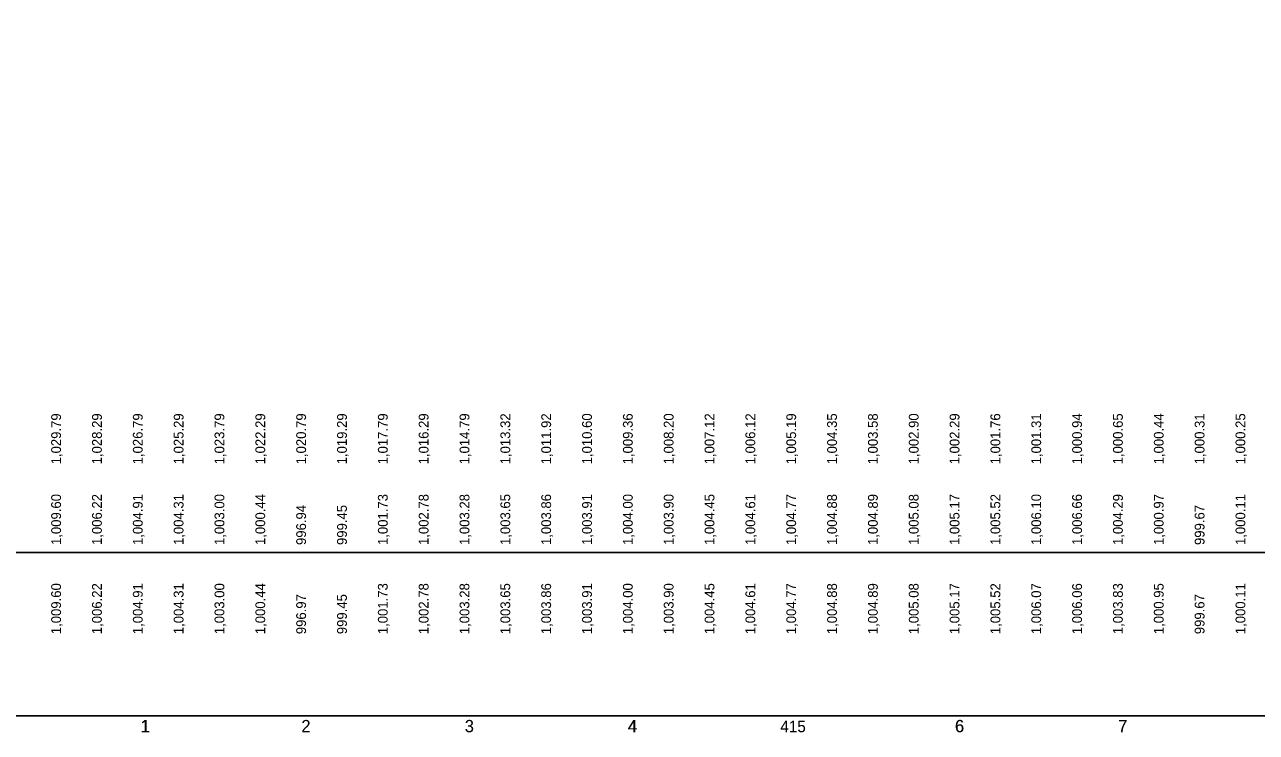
# Model space of a CAD drawing. Extents: x 150 to 16976893, y 3102 to 12559827.
# Drawn here: x 16975421 to 16976175, y 12558429 to 12558863 of the extents above; entities that cross this region are included whole.
import ezdxf

# ---------------------------------------------------------------- set-up
doc = ezdxf.new("R2010")
doc.units = 0
for name, color, linetype in [('Default', 7, 'Continuous'), ('Level 56', 7, 'Continuous'), ('RD_DDB_StaTX', 7, 'Continuous'), ('RD_DDB_StripGrade_EX', 7, 'Continuous'), ('RD_GPK_Profile_Cell', 7, 'Continuous')]:
    doc.layers.add(name, color=color, linetype=linetype)

msp = doc.modelspace()

# ---------------------------------------------------------------- linework, layer by layer
at = {"layer": 'Default'}
msp.add_lwpolyline([(16975392.9, 12558539.31), (16976892.9, 12558539.31), (16976892.9, 12559537.53), (16975392.9, 12559537.53)], close=True, dxfattribs=at)
at = {"layer": 'RD_GPK_Profile_Cell'}
msp.add_line((16972208.1, 12558439.31), (16976677.07, 12558439.31), dxfattribs=at)

# ---------------------------------------------------------------- texts
at = {"layer": 'Level 56'}
for s, p in [('1,029.79', (16975442.9, 12558593.29)), ('1,028.29', (16975467.9, 12558593.29)), ('1,026.79', (16975492.9, 12558593.29)), ('1,025.29', (16975517.9, 12558593.29)), ('1,023.79', (16975542.9, 12558593.29)), ('1,022.29', (16975567.9, 12558593.29)), ('1,020.79', (16975592.9, 12558593.29)), ('1,019.29', (16975617.9, 12558593.29)), ('1,017.79', (16975642.9, 12558593.29)), ('1,016.29', (16975667.9, 12558593.29)), ('1,014.79', (16975692.9, 12558593.29)), ('1,013.32', (16975717.9, 12558593.29)), ('1,011.92', (16975742.9, 12558593.29)), ('1,010.60', (16975767.9, 12558593.29)), ('1,009.36', (16975792.9, 12558593.29)), ('1,008.20', (16975817.9, 12558593.29)), ('1,007.12', (16975842.9, 12558593.29)), ('1,006.12', (16975867.9, 12558593.29)), ('1,005.19', (16975892.9, 12558593.29)), ('1,004.35', (16975917.9, 12558593.29)), ('1,003.58', (16975942.9, 12558593.29)), ('1,002.90', (16975967.9, 12558593.29)), ('1,002.29', (16975992.9, 12558593.29)), ('1,001.76', (16976017.9, 12558593.29)), ('1,001.31', (16976042.9, 12558593.29)), ('1,000.94', (16976067.9, 12558593.29)), ('1,000.65', (16976092.9, 12558593.29)), ('1,000.44', (16976117.9, 12558593.29)), ('1,000.31', (16976142.9, 12558593.29)), ('1,000.25', (16976167.9, 12558593.29)), ('1,009.60', (16975442.9, 12558489.31)), ('1,006.22', (16975467.9, 12558489.31)), ('1,004.91', (16975492.9, 12558489.31)), ('1,004.31', (16975517.9, 12558489.31)), ('1,003.00', (16975542.9, 12558489.31)), ('1,000.44', (16975567.9, 12558489.31)), ('1,001.73', (16975642.9, 12558489.31)), ('1,002.78', (16975667.9, 12558489.31)), ('1,003.28', (16975692.9, 12558489.31)), ('1,003.65', (16975717.9, 12558489.31)), ('1,003.86', (16975742.9, 12558489.31)), ('1,003.91', (16975767.9, 12558489.31)), ('1,004.00', (16975792.9, 12558489.31)), ('1,003.90', (16975817.9, 12558489.31)), ('1,004.45', (16975842.9, 12558489.31)), ('1,004.61', (16975867.9, 12558489.31)), ('1,004.77', (16975892.9, 12558489.31)), ('1,004.88', (16975917.9, 12558489.31)), ('1,004.89', (16975942.9, 12558489.31)), ('1,005.08', (16975967.9, 12558489.31)), ('1,005.17', (16975992.9, 12558489.31)), ('1,005.52', (16976017.9, 12558489.31)), ('1,006.07', (16976042.9, 12558489.31)), ('1,006.06', (16976067.9, 12558489.31)), ('1,003.83', (16976092.9, 12558489.31)), ('1,000.95', (16976117.9, 12558489.31)), ('1,000.11', (16976167.9, 12558489.31)), ('996.97', (16975592.9, 12558489.31)), ('999.45', (16975617.9, 12558489.31)), ('999.67', (16976142.9, 12558489.31))]:
    msp.add_text(s, height=6, rotation=90, dxfattribs=at).set_placement(p)
at = {"layer": 'RD_DDB_StaTX'}
for s, height, p in [('1', 7.5, (16975491.56, 12558429.31)), ('1', 7.5, (16975491.89, 12558429.31)), ('2', 7.5, (16975590.05, 12558429.31)), ('2', 7.5, (16975590.12, 12558429.31)), ('3', 7.5, (16975690.05, 12558429.31)), ('3', 7.5, (16975690.12, 12558429.31)), ('4', 7.5, (16975789.85, 12558429.31)), ('4', 7.5, (16975790.12, 12558429.31)), ('415', 7, (16975883.19, 12558429.31)), ('415', 7, (16975883.23, 12558429.31)), ('6', 7.5, (16975990.12, 12558429.31)), ('6', 7.5, (16975990.25, 12558429.31)), ('7', 7.5, (16976090.02, 12558429.31)), ('7', 7.5, (16976090.12, 12558429.31))]:
    msp.add_text(s, height=height, dxfattribs=at).set_placement(p)
at = {"layer": 'RD_DDB_StripGrade_EX'}
for s, p in [('1,009.60', (16975442.9, 12558543.9)), ('1,006.22', (16975467.9, 12558543.9)), ('1,004.91', (16975492.9, 12558543.9)), ('1,004.31', (16975517.9, 12558543.9)), ('1,003.00', (16975542.9, 12558543.9)), ('1,000.44', (16975567.9, 12558543.9)), ('996.94', (16975592.9, 12558543.9)), ('999.45', (16975617.9, 12558543.9)), ('1,001.73', (16975642.9, 12558543.9)), ('1,002.78', (16975667.9, 12558543.9)), ('1,003.28', (16975692.9, 12558543.9)), ('1,003.65', (16975717.9, 12558543.9)), ('1,003.86', (16975742.9, 12558543.9)), ('1,003.91', (16975767.9, 12558543.9)), ('1,004.00', (16975792.9, 12558543.9)), ('1,003.90', (16975817.9, 12558543.9)), ('1,004.45', (16975842.9, 12558543.9)), ('1,004.61', (16975867.9, 12558543.9)), ('1,004.77', (16975892.9, 12558543.9)), ('1,004.88', (16975917.9, 12558543.9)), ('1,004.89', (16975942.9, 12558543.9)), ('1,005.08', (16975967.9, 12558543.9)), ('1,005.17', (16975992.9, 12558543.9)), ('1,005.52', (16976017.9, 12558543.9)), ('1,006.10', (16976042.9, 12558543.9)), ('1,006.66', (16976067.9, 12558543.9)), ('1,004.29', (16976092.9, 12558543.9)), ('1,000.97', (16976117.9, 12558543.9)), ('999.67', (16976142.9, 12558543.9)), ('1,000.11', (16976167.9, 12558543.9))]:
    msp.add_text(s, height=6, rotation=90, dxfattribs=at).set_placement(p)

doc.saveas('drawing.dxf')
